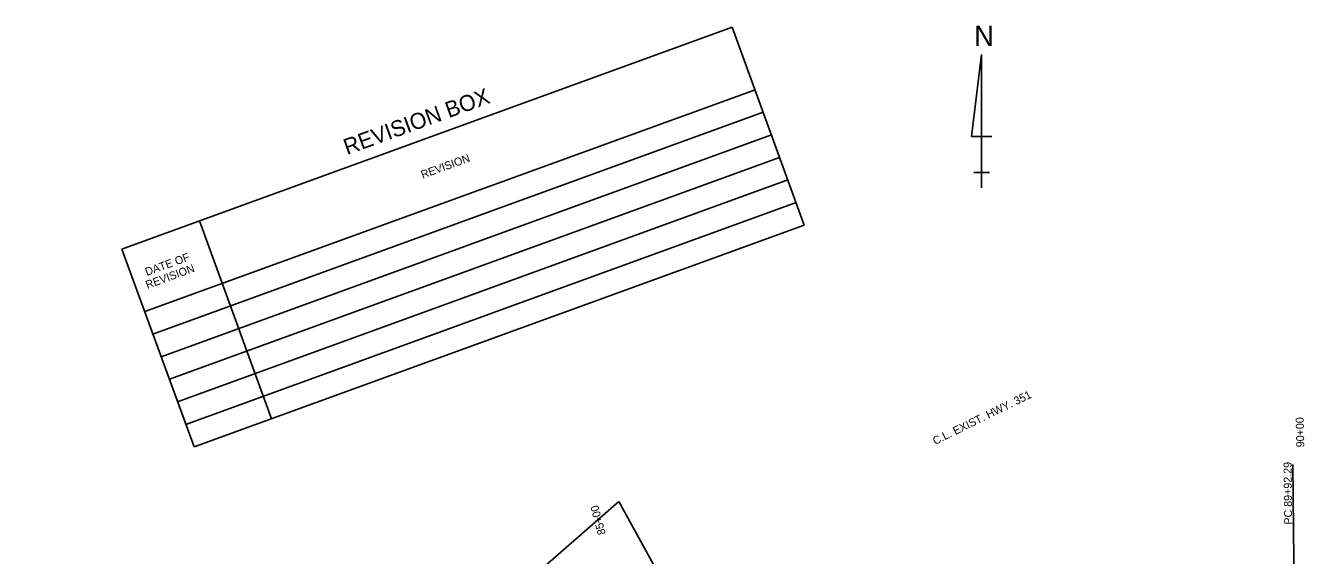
# Model space of a CAD drawing. Extents: x 1710782 to 1712392, y 548480 to 549912.
# Drawn here: x 1710782 to 1711740, y 549264 to 549662 of the extents above; entities that cross this region are included whole.
import ezdxf

# ---------------------------------------------------------------- set-up
doc = ezdxf.new("R2010")
doc.units = 0
for name, color, linetype in [('R_Contours', 7, 'Continuous'), ('R_Horz Alg', 7, 'Continuous'), ('R_Horz Alg Annot', 7, 'Continuous'), ('R_MOT', 7, 'Continuous')]:
    doc.layers.add(name, color=color, linetype=linetype)

msp = doc.modelspace()

# ---------------------------------------------------------------- linework, layer by layer
at = {"layer": 'R_Contours'}
msp.add_lwpolyline([(1711733, 549212.35), (1711731.65, 549332.35)], dxfattribs=at)
at = {"layer": 'R_Horz Alg'}
for p, q in [((1711498.42, 549639.96), (1711490.73, 549578.42)), ((1711498.42, 549539.96), (1711498.42, 549639.96)), ((1711498.42, 549639.96), (1711498.42, 549563.04)), ((1711490.73, 549578.42), (1711506.11, 549578.42)), ((1711498.42, 549539.96), (1711498.42, 549563.04)), ((1711498.42, 549551.5), (1711492.65, 549551.5)), ((1711492.65, 549551.5), (1711504.19, 549551.5)), ((1711498.42, 549539.96), (1711498.42, 549551.5))]:
    msp.add_line(p, q, dxfattribs=at)
at = {"layer": 'R_Horz Alg Annot'}
for p, q in [((1710853.98, 549494.04), (1711311.43, 549660.53)), ((1711311.43, 549660.53), (1711365.47, 549512.06)), ((1710871.08, 549447.05), (1711328.53, 549613.55)), ((1710877.24, 549430.14), (1711334.69, 549596.64)), ((1710883.39, 549413.22), (1711340.84, 549579.72)), ((1710889.55, 549396.31), (1711347, 549562.81)), ((1710895.71, 549379.39), (1711353.16, 549545.89)), ((1710901.86, 549362.48), (1711359.31, 549528.98)), ((1710908.02, 549345.57), (1711365.47, 549512.06)), ((1710912.06, 549515.18), (1710966.1, 549366.71)), ((1710853.98, 549494.04), (1710908.02, 549345.57))]:
    msp.add_line(p, q, dxfattribs=at)
at = {"layer": 'R_MOT'}
for p, q in [((1710781.74, 548916.29), (1711226.5, 549304.64)), ((1711226.5, 549304.64), (1711265.68, 549233.34))]:
    msp.add_line(p, q, dxfattribs=at)

# ---------------------------------------------------------------- texts
at = {"layer": 'R_Contours'}
for s, rotation, p in [('90+00', 91.47143, (1711740.33, 549345.38)), ('PC 89+92.29', 90.64281, (1711731.22, 549287.28)), ('85+00', 104.99186, (1711216.7, 549280.48))]:
    msp.add_text(s, height=6, rotation=rotation, dxfattribs=at).set_placement(p)
at = {"layer": 'R_Horz Alg'}
msp.add_text('N', height=15.38, dxfattribs=at).set_placement((1711492.79, 549646.37))
at = {"layer": 'R_Horz Alg Annot'}
for s, height, rotation, p in [('REVISION BOX', 12, 20, (1711022.71, 549564.49)), ('REVISION', 6, 20, (1711079.39, 549546.81)), ('DATE OF', 6, 20, (1710872.66, 549473.83)), ('REVISION', 6, 20, (1710873, 549464.11)), ('C.L. EXIST. HWY. 351', 6, 26.16666, (1711463.52, 549346.96))]:
    msp.add_text(s, height=height, rotation=rotation, dxfattribs=at).set_placement(p)

doc.saveas('drawing.dxf')
